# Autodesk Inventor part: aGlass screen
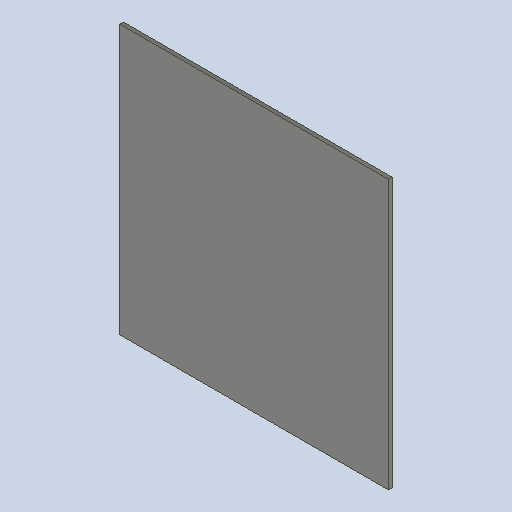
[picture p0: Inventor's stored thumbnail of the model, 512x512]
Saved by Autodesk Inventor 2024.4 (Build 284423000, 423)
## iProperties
Created: 2025-04
Part Number: aGlass screen
Material: Generic
Document SubType Name: Modeling
Designer: AdminForWorker
Density: 1 g/cm^3
Appearance: Default
Title: aGlass screen v3
Author: AdminForWorker
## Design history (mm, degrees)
feature "Body1"
body "Solid1"
